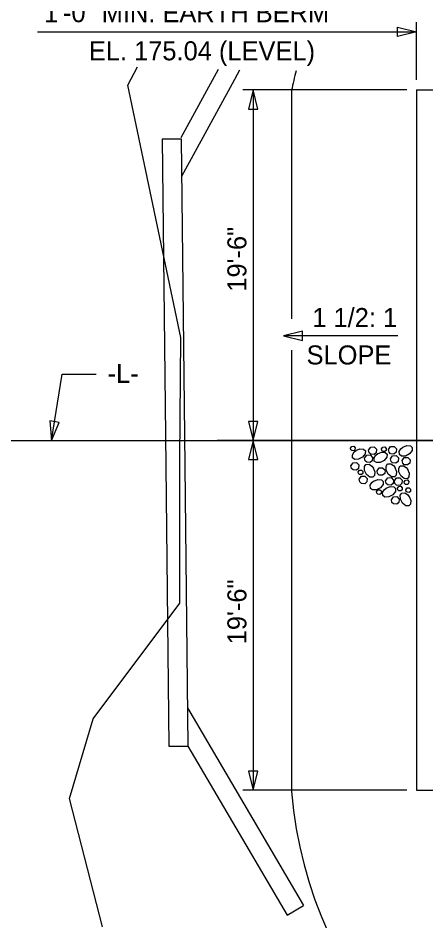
# Model space of a CAD drawing. Extents: x 985 to 1514, y -701 to -21.
# Drawn here: x 1132.56 to 1154, y -184.23 to -136.79 of the extents above; entities that cross this region are included whole.
import ezdxf

# ---------------------------------------------------------------- set-up
doc = ezdxf.new("R2010")
doc.units = 0
for name, color, linetype in [('Arrowhead Terminators CELL', 7, 'Continuous'), ('Auto Dimensioning', 7, 'Continuous'), ('Dimension Lines', 7, 'Continuous'), ('Exist Hydro Stream or Body of Water', 7, 'Continuous'), ('Exist Structure Major Bridge Seam', 7, 'Continuous'), ('Mis -L- Lines', 7, 'Continuous'), ('Mis Object Lines', 7, 'Continuous'), ('Miscellaneous Lines CELL', 7, 'Continuous'), ('Sub End Bent Cap Lines CELL', 7, 'Continuous'), ('Sup Concrete Girder Lines', 7, 'Continuous'), ('Text', 7, 'Continuous')]:
    doc.layers.add(name, color=color, linetype=linetype)

# ---------------------------------------------------------------- blocks, each defined once
blk = doc.blocks.new('AH')
at = {"layer": 'Sub End Bent Cap Lines CELL'}
blk.add_lwpolyline([(0, 0), (-1.25, 0.312), (-1.25, -0.312)], close=True, dxfattribs=at)

msp = doc.modelspace()

# ---------------------------------------------------------------- linework, layer by layer
at = {"layer": 'Arrowhead Terminators CELL'}
for points in [[(1146.504, -153.489), (1147.504, -153.739), (1147.504, -153.239)], [(1134.309, -158.986), (1134.715, -158.038), (1134.221, -157.959)]]:
    msp.add_lwpolyline(points, close=True, dxfattribs=at)
at = {"layer": 'Auto Dimensioning'}
for p, q in [((1153.002, -140.569), (1144.373, -140.569)), ((1144.915, -140.569), (1144.915, -158.986)), ((1156.752, -158.986), (1143.03, -158.986)), ((1144.915, -158.986), (1144.915, -177.358)), ((1153.002, -177.358), (1144.373, -177.358))]:
    msp.add_line(p, q, dxfattribs=at)
at = {"layer": 'Dimension Lines'}
for p, q in [((1153.502, -140.029), (1153.502, -137.01)), ((1133.583, -137.51), (1153.502, -137.51)), ((1152.526, -153.489), (1146.504, -153.489)), ((1134.309, -158.986), (1134.869, -155.505)), ((1134.869, -155.505), (1136.671, -155.505))]:
    msp.add_line(p, q, dxfattribs=at)
at = {"layer": 'Exist Hydro Stream or Body of Water'}
for points in [[(1138.334, -140.321), (1138.829, -139.359)], [(1136.509, -173.615), (1141.067, -167.522), (1141.059, -159.959), (1141.114, -153.58), (1138.334, -140.321)], [(1136.995, -184.536), (1135.256, -177.797), (1136.509, -173.615)]]:
    msp.add_lwpolyline(points, dxfattribs=at)
at = {"layer": 'Exist Structure Major Bridge Seam'}
for p, q in [((1141.13, -143.062), (1143.094, -139.482)), ((1143.827, -140.226), (1144.217, -139.515)), ((1141.159, -145.089), (1143.827, -140.226)), ((1140.138, -143.128), (1141.138, -143.128)), ((1141.458, -173.027), (1143.004, -175.657)), ((1140.486, -175.047), (1141.486, -175.047)), ((1141.486, -175.047), (1146.707, -183.929)), ((1143.004, -175.657), (1147.569, -183.423)), ((1146.707, -183.929), (1147.569, -183.423))]:
    msp.add_line(p, q, dxfattribs=at)
for points in [[(1140.138, -143.128), (1140.307, -158.702), (1140.486, -175.047)], [(1141.138, -143.128), (1141.307, -158.702), (1141.486, -175.047)]]:
    msp.add_lwpolyline(points, dxfattribs=at)
at = {"layer": 'Mis -L- Lines'}
msp.add_line((1058.329, -158.986), (1185.585, -158.986), dxfattribs=at)
at = {"layer": 'Mis Object Lines'}
for p, q in [((1153.502, -140.569), (1168.122, -140.569)), ((1153.502, -140.569), (1153.502, -177.358)), ((1153.502, -177.358), (1168.122, -177.358))]:
    msp.add_line(p, q, dxfattribs=at)
at = {"layer": 'Miscellaneous Lines CELL'}
for points in [[(1150.032, -159.386), (1150.099, -159.291), (1150.206, -159.285), (1150.281, -159.362), (1150.27, -159.47), (1150.204, -159.526), (1150.098, -159.518), (1150.048, -159.47), (1150.032, -159.386)], [(1150.986, -159.489), (1151.098, -159.329), (1151.277, -159.319), (1151.401, -159.448), (1151.383, -159.629), (1151.273, -159.721), (1151.096, -159.708), (1151.013, -159.627), (1150.986, -159.489)], [(1151.666, -159.423), (1151.733, -159.328), (1151.84, -159.321), (1151.915, -159.399), (1151.904, -159.507), (1151.838, -159.562), (1151.732, -159.555), (1151.682, -159.506), (1151.666, -159.423)], [(1152.033, -159.464), (1152.145, -159.305), (1152.324, -159.295), (1152.448, -159.424), (1152.43, -159.605), (1152.32, -159.696), (1152.143, -159.684), (1152.06, -159.603), (1152.033, -159.465)], [(1152.785, -159.337), (1152.995, -159.254), (1153.187, -159.271), (1153.279, -159.358), (1153.276, -159.514), (1153.137, -159.691), (1152.922, -159.799), (1152.72, -159.802), (1152.606, -159.721), (1152.595, -159.56), (1152.688, -159.416), (1152.793, -159.332)], [(1150.322, -159.509), (1150.532, -159.426), (1150.724, -159.443), (1150.816, -159.53), (1150.813, -159.686), (1150.674, -159.863), (1150.459, -159.971), (1150.257, -159.974), (1150.143, -159.893), (1150.132, -159.732), (1150.225, -159.588), (1150.331, -159.504)], [(1150.775, -159.91), (1150.887, -159.751), (1151.066, -159.741), (1151.191, -159.87), (1151.173, -160.05), (1151.062, -160.142), (1150.885, -160.13), (1150.802, -160.049), (1150.775, -159.91)], [(1151.461, -159.679), (1151.671, -159.595), (1151.863, -159.612), (1151.955, -159.699), (1151.952, -159.855), (1151.813, -160.033), (1151.598, -160.14), (1151.396, -160.144), (1151.282, -160.063), (1151.271, -159.902), (1151.364, -159.758), (1151.469, -159.673)], [(1152.139, -159.942), (1152.251, -159.782), (1152.429, -159.772), (1152.554, -159.901), (1152.536, -160.082), (1152.425, -160.174), (1152.249, -160.161), (1152.166, -160.08), (1152.139, -159.942)], [(1150.057, -160.31), (1150.169, -160.151), (1150.348, -160.141), (1150.472, -160.27), (1150.454, -160.45), (1150.343, -160.542), (1150.167, -160.529), (1150.084, -160.449), (1150.057, -160.31)], [(1151.233, -160.423), (1151.316, -160.632), (1151.299, -160.825), (1151.212, -160.917), (1151.056, -160.914), (1150.879, -160.775), (1150.771, -160.56), (1150.768, -160.358), (1150.849, -160.244), (1151.01, -160.233), (1151.154, -160.325), (1151.238, -160.431)], [(1152.372, -160.396), (1152.455, -160.605), (1152.438, -160.798), (1152.351, -160.889), (1152.195, -160.886), (1152.017, -160.748), (1151.91, -160.533), (1151.906, -160.331), (1151.987, -160.217), (1152.149, -160.206), (1152.293, -160.298), (1152.377, -160.404)], [(1153.036, -160.497), (1153.119, -160.707), (1153.102, -160.9), (1153.015, -160.991), (1152.859, -160.988), (1152.682, -160.849), (1152.574, -160.635), (1152.571, -160.432), (1152.652, -160.318), (1152.813, -160.308), (1152.957, -160.4), (1153.041, -160.506)], [(1152.751, -160.039), (1152.863, -159.88), (1153.042, -159.87), (1153.166, -159.999), (1153.148, -160.179), (1153.038, -160.271), (1152.861, -160.258), (1152.778, -160.178), (1152.751, -160.039)], [(1150.442, -160.637), (1150.509, -160.541), (1150.616, -160.535), (1150.691, -160.612), (1150.68, -160.721), (1150.614, -160.776), (1150.508, -160.768), (1150.458, -160.72), (1150.442, -160.637)], [(1151.434, -160.581), (1151.546, -160.422), (1151.725, -160.412), (1151.849, -160.541), (1151.831, -160.721), (1151.721, -160.813), (1151.544, -160.801), (1151.461, -160.72), (1151.434, -160.581)], [(1150.499, -161.022), (1150.611, -160.863), (1150.79, -160.852), (1150.914, -160.981), (1150.896, -161.162), (1150.786, -161.254), (1150.609, -161.241), (1150.526, -161.161), (1150.499, -161.022)], [(1151.258, -161.116), (1151.467, -161.032), (1151.66, -161.049), (1151.751, -161.136), (1151.748, -161.292), (1151.609, -161.47), (1151.395, -161.577), (1151.193, -161.581), (1151.079, -161.5), (1151.068, -161.339), (1151.16, -161.195), (1151.266, -161.11)], [(1151.883, -161.101), (1151.995, -160.942), (1152.174, -160.931), (1152.298, -161.06), (1152.28, -161.241), (1152.169, -161.333), (1151.993, -161.32), (1151.91, -161.24), (1151.883, -161.101)], [(1152.344, -161.108), (1152.456, -160.948), (1152.634, -160.938), (1152.759, -161.067), (1152.741, -161.248), (1152.63, -161.34), (1152.454, -161.327), (1152.371, -161.246), (1152.344, -161.108)], [(1152.853, -161.157), (1152.921, -161.061), (1153.028, -161.055), (1153.103, -161.133), (1153.092, -161.241), (1153.025, -161.296), (1152.919, -161.288), (1152.87, -161.24), (1152.853, -161.157)], [(1151.408, -161.677), (1151.476, -161.582), (1151.583, -161.575), (1151.658, -161.653), (1151.647, -161.761), (1151.581, -161.816), (1151.475, -161.809), (1151.425, -161.76), (1151.409, -161.677)], [(1151.908, -161.49), (1152.118, -161.407), (1152.31, -161.424), (1152.402, -161.511), (1152.399, -161.667), (1152.26, -161.844), (1152.045, -161.952), (1151.843, -161.955), (1151.729, -161.874), (1151.718, -161.713), (1151.811, -161.569), (1151.916, -161.485)], [(1152.507, -161.493), (1152.574, -161.398), (1152.681, -161.391), (1152.756, -161.469), (1152.745, -161.577), (1152.679, -161.632), (1152.573, -161.625), (1152.523, -161.576), (1152.507, -161.493)], [(1153.117, -161.928), (1153.2, -162.137), (1153.184, -162.33), (1153.097, -162.421), (1152.94, -162.418), (1152.763, -162.279), (1152.656, -162.065), (1152.652, -161.863), (1152.733, -161.749), (1152.894, -161.738), (1153.038, -161.83), (1153.123, -161.936)], [(1152.948, -161.572), (1153.015, -161.476), (1153.122, -161.47), (1153.197, -161.548), (1153.186, -161.656), (1153.12, -161.711), (1153.014, -161.704), (1152.964, -161.655), (1152.948, -161.572)], [(1152.182, -162.098), (1152.294, -161.939), (1152.473, -161.929), (1152.598, -162.058), (1152.58, -162.238), (1152.469, -162.33), (1152.293, -162.317), (1152.209, -162.237), (1152.183, -162.098)]]:
    msp.add_lwpolyline(points, dxfattribs=at)
at = {"layer": 'Sup Concrete Girder Lines'}
for p, q in [((1146.934, -140.601), (1146.934, -152.595)), ((1146.934, -154.245), (1146.934, -177.434))]:
    msp.add_line(p, q, dxfattribs=at)
for centre, radius, start, end in [((1166.327, -144.57), 19.795, 165.3232, 168.4317), ((1169.597, -175.48), 22.747, 184.9278, 261.7748)]:
    msp.add_arc(centre, radius, start, end, dxfattribs=at)

# ---------------------------------------------------------------- block references
at = {"layer": 'Arrowhead Terminators CELL', "xscale": 0.8, "yscale": -0.8000000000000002}
msp.add_blockref('AH', (1153.502, -137.51), dxfattribs=at)
at = {"layer": 'Auto Dimensioning', "xscale": 0.8, "yscale": 0.8000000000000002}
for p, rotation in [((1144.915, -140.569), 90), ((1144.915, -158.986), -90), ((1144.915, -158.986), 90), ((1144.915, -177.358), -90)]:
    msp.add_blockref('AH', p, dxfattribs=dict(at, rotation=rotation))

# ---------------------------------------------------------------- texts
at = {"layer": 'Dimension Lines'}
msp.add_text('-L-', height=1, dxfattribs=at).set_placement((1137.265, -155.958))
at = {"layer": 'Text'}
for s, p in [('1\'-0" MIN. EARTH BERM', (1133.918, -137.01)), ('EL. 175.04 (LEVEL)', (1136.277, -139.01)), ('1 1/2: 1', (1148.025, -153.024)), ('SLOPE', (1147.724, -154.989))]:
    msp.add_text(s, height=1, dxfattribs=at).set_placement(p)
for p in [(1144.562, -151.167), (1144.562, -169.692)]:
    msp.add_text('19\'-6"', height=1, rotation=90, dxfattribs=at).set_placement(p)

doc.saveas('drawing.dxf')
